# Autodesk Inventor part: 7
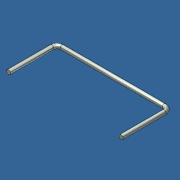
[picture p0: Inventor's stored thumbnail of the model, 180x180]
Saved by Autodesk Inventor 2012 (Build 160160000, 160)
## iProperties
Created: 2013-04
Part Number: 7
Material: Steel
Document SubType Name: Modeling
Designer: Admin
Density: 7.85 g/cm^3
Mass: 19.2072 g
Surface Area: 24.7191 cm^2
Volume: 2.44677 cm^3
Author: Admin
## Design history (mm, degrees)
node "71"
node "7"
node "Base1"
